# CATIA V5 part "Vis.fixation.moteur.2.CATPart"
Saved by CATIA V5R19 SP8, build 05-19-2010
Part number: Vis.fixation.moteur.2
Bounding box of the stored display mesh (mm): x 13.5 to 16.5, y -17 to -11, z -1.5 to 1.5
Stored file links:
  G:\EU_thinkMotion\CFAO_2010\MMS_groupe3\MMS_groupe3\jbonnamy\jbonnamy_cfao\Vis.fixation.moteur.2.CATPart
  C:\Users\Micheline\Desktop\projet CFAO\Nouveau dossier\temp\Nouveau dossier\Vis.fixation.CATPart
  G:\EU_thinkMotion\CFAO_2010\MMS_groupe3\MMS_groupe3\jbonnamy\jbonnamy_cfao\jbonnamy_suspension.arriere.directionnelle.CATProduct
  G:\EU_thinkMotion\CFAO_2010\MMS_groupe3\MMS_groupe3\jbonnamy\jbonnamy_cfao\Vis.fixation.moteur.1.CATPart
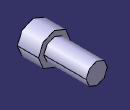
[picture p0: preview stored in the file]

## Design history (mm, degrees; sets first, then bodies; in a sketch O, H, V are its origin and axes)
External parameters (linked from other documents)
  External.Epaisseur.support.10 = 1.5 mm
  External.Diametre.vis.fixation = 2 mm
Set1
  DatumSurface1: linked copy from another document
Body1 (main body)
  Sketch1 on DatumSurface1, origin (15, -15, 0), H (1, 0, 0), V (0, 0, 1)
    circle A1 centre (0, 0) radius 1
    radius A1 = 1 {= External.Diametre.vis.fixation /2}
  Pad1: profile Sketch1, direction (0, 1, 0), length 4 {= 2*External.Epaisseur.support.10 +1mm}
  Sketch2 on DatumSurface1, origin (15, -15, 0), H (1, 0, 0), V (0, 0, 1)
    circle A1 centre (0, 0) radius 1.5
    radius A1 = 1.5 {= 3*External.Diametre.vis.fixation /4}
  Pad2: profile Sketch2, direction (0, -1, 0), length 2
